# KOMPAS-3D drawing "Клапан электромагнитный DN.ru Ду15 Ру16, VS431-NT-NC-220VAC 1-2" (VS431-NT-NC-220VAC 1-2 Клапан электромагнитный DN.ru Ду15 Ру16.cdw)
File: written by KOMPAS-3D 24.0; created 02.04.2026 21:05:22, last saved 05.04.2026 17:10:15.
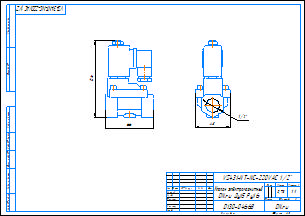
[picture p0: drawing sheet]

Document properties: c3d_UniqueCompID: ef56311e-7521-43dc-8291-0e6108b3d81d; Обозначение: VS400-ET-NC-220VAC 1-2; Наименование: Клапан электромагнитный DN.ru Ду15 Ру16; Автор: artio; Класс точности: c; Знак неуказанной шероховатости: Шероховатость не задана; Рассекать на разрезах: Да; c3d_UniqueCompID: ef56311e-7521-43dc-8291-0e6108b3d81d; Обозначение: VS400-ET-NC-220VAC 3-8; Наименование: Клапан электромагнитный DN.ru Ду10 Ру16; Автор: artio; Класс точности: c; Знак неуказанной шероховатости: Шероховатость не задана; Рассекать на разрезах: Да; Автор: artio; Форматы листов документа: A3; Полное имя файла: VS431-NT-NC-220VAC 1-2 Клапан электромагнитный DN.ru Ду15 Ру16.m3d; Масса: 0.732; Наименование: Клапан электромагнитный DN.ru Ду15 Ру16; Количество листов документа: 1; Примечание: D130-04661

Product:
- Body: Тело 1  | qty 1
    Масса: 1.030062
- Part/product: Клапан электромагнитный DN.ru Ду15 Ру16  | designation VS431-NT-NC-220VAC 1-2
    Масса: 0.732
    Раздел спецификации: Прочие изделия
    Примечание: D130-04661
    additional columns: ef56311e-7521-43dc-8291-0e6108b3d81d; VS400-ET-NC-220VAC 1-2; artio; c; Шероховатость не задана; Да

Views: Вид 1, Спереди, Проекционный вид 2
Referenced files in C:\Users\artio\OneDrive\Рабочий стол\Клапан электромагнитный DN.ru VS4x-xT-NC-x\DN10\: VS400-ET-NC-220VAC 3-8 Клапан электромагнитный DN.ru Ду10 Ру16.m3d, VS400-ET-NC-220VAC 3-8 Клапан электромагнитный DN.ru Ду10 Ру16.cdw
Referenced files in C:\Users\artio\OneDrive\Рабочий стол\Клапан электромагнитный DN.ru\VS431\VS431-NT-NC\VS431-NT-NC-220VAC\Ду15\: VS431-NT-NC-220VAC 1-2 Клапан электромагнитный DN.ru Ду15 Ру16.m3d
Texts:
  VS431-NT-NC-220VAC 1-2
  Линейный размер
  Клапан электромагнитный
  DN.ru Ду15 Ру16
  VS431-NT-NC-220VAC 1/2"
  VS431-NT-NC-220VAC 1/2"-
  Клапан электромагнитный DN.ru Ду15 Ру16
  VS431-NT-NC-220VAC 1-2 Клапан электромагнитный DN.ru Ду15 Ру16
Dimensions and other numbers on the sheet: 0; 3; 2; 4; 48; 1/2"; 66; 106; 1:1; 1; 0,73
